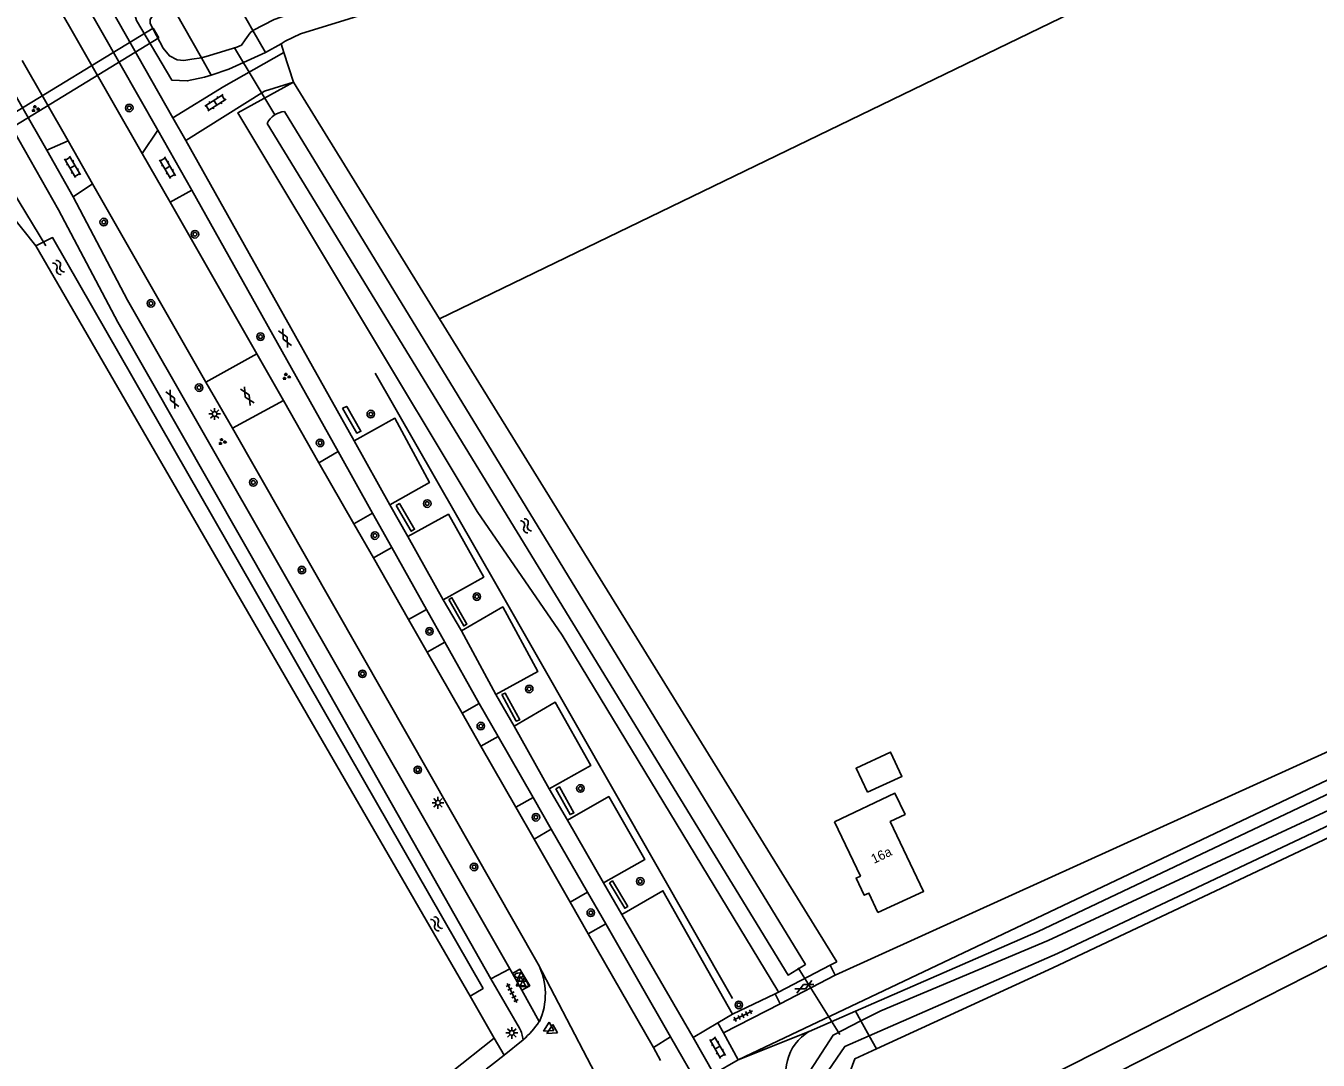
# Model space of a CAD drawing. Extents: x 134297 to 137000, y 403500 to 406000.
# Drawn here: x 136760.9 to 136897.8, y 403591.7 to 403701.3 of the extents above; entities that cross this region are included whole.
import ezdxf

# ---------------------------------------------------------------- set-up
doc = ezdxf.new("R2010")
doc.units = 0
for name, color, linetype in [('gg-afsc-erfafscheiding', 7, 'Continuous'), ('gg-anno-huisnummerreeks BGT', 7, 'Continuous'), ('gg-bbg-bijgebouw', 7, 'Continuous'), ('gg-bbg-gedigitaliseerde bebouwing', 7, 'Continuous'), ('gg-bbg-hoofdgebouw', 7, 'Continuous'), ('gg-knt-bronhoudergrens', 7, 'Continuous'), ('gg-knt-onverhard', 7, 'Continuous'), ('gg-knt-verharding', 7, 'Continuous'), ('gg-kntw-bovenkant insteek waterloop', 7, 'Continuous'), ('gg-kntw-waterlijn', 7, 'Continuous'), ('gg-kwrk-duiker nz buis', 7, 'Continuous'), ('gg-kwrk-duiker nz vlak', 7, 'Continuous'), ('gt-afsc-boombescherming', 7, 'Continuous'), ('gt-grn-groengrens', 7, 'Continuous'), ('gt-grn-vlakafsluiter', 7, 'Continuous'), ('gt-grn-weggrens', 7, 'Continuous'), ('gt-symb-boom', 7, 'Continuous'), ('gt-symb-brandkraan', 7, 'Continuous'), ('gt-symb-gesloten verharding', 7, 'Continuous'), ('gt-symb-groenvak', 7, 'Continuous'), ('gt-symb-klinker verharding', 7, 'Continuous'), ('gt-symb-lichtmast', 7, 'Continuous'), ('gt-symb-tegel verharding', 7, 'Continuous'), ('gt-symb-waterafsluiter', 7, 'Continuous'), ('gt-symb-watersymbool', 7, 'Continuous')]:
    doc.layers.add(name, color=color, linetype=linetype)

# ---------------------------------------------------------------- blocks, each defined once
blk = doc.blocks.new('gt0-BOOM')
at = {"layer": 'gt-symb-boom'}
for radius in [0.4, 0.2]:
    blk.add_circle((0, 0), radius, dxfattribs=at)
blk = doc.blocks.new('gt0-TEG1')
at = {"layer": 'gt-symb-tegel verharding'}
for p, q in [((-1.12, 0), (1.12, 0)), ((-0.9, -0.25), (-0.9, 0.25)), ((-0.45, -0.25), (-0.45, 0.25)), ((0, -0.25), (0, 0.25)), ((0.45, -0.25), (0.45, 0.25)), ((0.9, -0.25), (0.9, 0.25))]:
    blk.add_line(p, q, dxfattribs=at)
blk = doc.blocks.new('gt0-KL1')
at = {"layer": 'gt-symb-klinker verharding'}
for p, q in [((-1.15, 0.3), (1.15, 0.3)), ((-1, -0.3), (-1, 0.3)), ((-0.5, 0.3), (-0.5, 0.45)), ((0, -0.3), (0, 0.3)), ((0.5, 0.3), (0.5, 0.45)), ((1, -0.3), (1, 0.3)), ((-1.15, -0.3), (1.15, -0.3)), ((-0.5, -0.45), (-0.5, -0.3)), ((0.5, -0.45), (0.5, -0.3))]:
    blk.add_line(p, q, dxfattribs=at)
blk = doc.blocks.new('gt0-GESVH1')
at = {"layer": 'gt-symb-gesloten verharding'}
for p, q in [((-0.99, -0.26), (0.01, 0.24)), ((0.01, -0.26), (-0.99, 0.24)), ((0.01, 0.24), (1.01, -0.26)), ((1.01, 0.24), (0.01, -0.26))]:
    blk.add_line(p, q, dxfattribs=at)
blk = doc.blocks.new('gt0-BR')
at = {"layer": 'gt-symb-brandkraan'}
for centre, radius, start, end in [((-0.24, 0), 0.206, 107.5669, 252.4331), ((0.6, -2.66), 3, 106.892, 107.5669), ((0, -0.69), 0.938, 73.108, 106.892), ((-0.6, -2.66), 3, 72.4331, 73.108), ((0.24, 0), 0.206, 287.567, 72.4331), ((0.6, 2.66), 3, 252.4331, 253.108), ((0, 0.69), 0.938, 253.108, 286.8921), ((-0.6, 2.66), 3, 286.8921, 287.567)]:
    blk.add_arc(centre, radius, start, end, dxfattribs=at)
blk = doc.blocks.new('gt0-WAFSL')
at = {"layer": 'gt-symb-waterafsluiter'}
for p, q in [((-0.5, -0.33), (0, 0.67)), ((0, 0.67), (0.5, -0.33)), ((0.5, -0.33), (-0.5, -0.33))]:
    blk.add_line(p, q, dxfattribs=at)
blk = doc.blocks.new('gt0-LMAST')
at = {"layer": 'gt-symb-lichtmast'}
for p, q in [((-0.18, 0.17), (-0.45, 0.44)), ((-0.01, 0.25), (-0.01, 0.62)), ((0.17, 0.17), (0.44, 0.44)), ((-0.26, 0), (-0.63, 0)), ((-0.18, -0.18), (-0.45, -0.45)), ((-0.01, -0.25), (-0.01, -0.63)), ((0.44, -0.45), (0.17, -0.18)), ((0.24, 0), (0.62, 0))]:
    blk.add_line(p, q, dxfattribs=at)
blk.add_circle((-0.01, 0), 0.25, dxfattribs=at)
blk = doc.blocks.new('gt0-WA')
at = {"layer": 'gt-symb-watersymbool'}
for centre, start, end in [((-0.32, 0.02), 28.0725, 151.9275), ((0.43, 0.42), 208.0725, 331.9275), ((-0.32, -0.43), 28.0725, 151.9275), ((0.43, -0.03), 208.0725, 331.9275)]:
    blk.add_arc(centre, 0.425, start, end, dxfattribs=at)
blk = doc.blocks.new('gt0-GRVAK')
at = {"layer": 'gt-symb-groenvak'}
for p, q in [((-0.11, 0.19), (-0.23, 0.24)), ((-0.18, 0.15), (0.09, 0.15)), ((-0.09, 0.21), (-0.16, 0.32)), ((-0.05, 0.21), (-0.05, 0.39)), ((0, 0.21), (0.06, 0.32)), ((0.01, 0.19), (0.13, 0.24)), ((0.26, -0.05), (0.2, 0.06)), ((0.3, -0.05), (0.3, 0.13)), ((0.35, -0.05), (0.41, 0.06)), ((-0.24, -0.23), (-0.36, -0.18)), ((-0.32, -0.26), (-0.05, -0.26)), ((-0.23, -0.21), (-0.29, -0.09)), ((-0.18, -0.2), (-0.18, -0.02)), ((-0.14, -0.21), (-0.07, -0.09)), ((-0.12, -0.23), (0, -0.18)), ((0.24, -0.07), (0.12, -0.02)), ((0.17, -0.11), (0.44, -0.11)), ((0.37, -0.07), (0.49, -0.02))]:
    blk.add_line(p, q, dxfattribs=at)

msp = doc.modelspace()

# ---------------------------------------------------------------- linework, layer by layer
at = {"layer": 'gg-afsc-erfafscheiding'}
for q in [(136797.89, 403664.49), (136835.74, 403598.27)]:
    msp.add_line((136810.83, 403641.95), q, dxfattribs=at)
at = {"layer": 'gg-bbg-bijgebouw'}
msp.add_lwpolyline([(136850.05, 403620.11), (136848.82, 403622.65), (136852.49, 403624.36), (136853.69, 403621.79), (136850.05, 403620.11)], dxfattribs=at)
at = {"layer": 'gg-bbg-gedigitaliseerde bebouwing'}
msp.add_lwpolyline([(136846.56, 403616.96), (136852.94, 403620), (136854.02, 403617.76), (136852.44, 403617), (136855.98, 403609.61), (136851.13, 403607.38)], dxfattribs=at)
at = {"layer": 'gg-bbg-hoofdgebouw'}
msp.add_lwpolyline([(136851.13, 403607.38), (136850.18, 403609.43), (136849.69, 403609.2), (136848.83, 403611.01), (136849.29, 403611.23), (136846.56, 403616.96)], dxfattribs=at)
at = {"layer": 'gg-knt-bronhoudergrens'}
msp.add_line((136761.94, 403677.98), (136757.48, 403683.6), dxfattribs=at)
msp.add_lwpolyline([(136804.72, 403670.25), (136922.89, 403727.53), (136948.48, 403735.49), (136972.38, 403746.38), (137000, 403761.19)], dxfattribs=at)
at = {"layer": 'gg-knt-onverhard'}
msp.add_line((136836.35, 403591.75), (137000, 403669.55), dxfattribs=at)
for points in [[(136846.62, 403600.72), (136864.98, 403609.06), (136937.04, 403641.78), (137000, 403672.86)], [(137000, 403651.88), (136926.75, 403614.91), (136915.2, 403613.35), (136861.96, 403586.32), (136863.28, 403583.72), (136916.67, 403610.83), (136928.06, 403612.07), (137000, 403647.8)]]:
    msp.add_lwpolyline(points, dxfattribs=at)
at = {"layer": 'gg-knt-verharding'}
for p, q in [((136730.84, 403771.71), (136776.48, 403691.56)), ((136729.23, 403770.34), (136774.89, 403690.26)), ((136726.83, 403768.98), (136773.23, 403687.76)), ((136788.21, 403698.47), (136781.87, 403694.86)), ((136788.21, 403698.47), (136789.24, 403695.32)), ((136757.66, 403697.63), (136763.11, 403688.11)), ((136760.51, 403697.64), (136765.37, 403689.12)), ((136776.48, 403691.56), (136781.87, 403694.86)), ((136777.83, 403689.16), (136786.18, 403694.38)), ((136776.48, 403691.56), (136777.83, 403689.16)), ((136773.23, 403687.76), (136774.89, 403690.26)), ((136778.46, 403683.9), (136774.89, 403690.26)), ((136765.37, 403689.12), (136763.11, 403688.11)), ((136765.37, 403689.12), (136767.97, 403684.57)), ((136777.83, 403689.16), (136795.66, 403657.34)), ((136765.92, 403683.19), (136763.11, 403688.11)), ((136776.18, 403682.61), (136773.23, 403687.76)), ((136765.92, 403683.19), (136767.97, 403684.57)), ((136767.97, 403684.57), (136779.97, 403663.56)), ((136778.46, 403683.9), (136776.18, 403682.61)), ((136793.98, 403656.19), (136778.46, 403683.9)), ((136785.35, 403666.55), (136776.18, 403682.61)), ((136779.97, 403663.56), (136785.35, 403666.55)), ((136788.17, 403661.61), (136785.35, 403666.55)), ((136779.97, 403663.56), (136782.77, 403658.67)), ((136788.17, 403661.61), (136782.77, 403658.67)), ((136791.93, 403655.02), (136788.17, 403661.61)), ((136782.77, 403658.67), (136798.96, 403630.33)), ((136795.66, 403657.34), (136799.46, 403650.57)), ((136793.98, 403656.19), (136791.93, 403655.02)), ((136797.62, 403649.68), (136793.98, 403656.19)), ((136795.62, 403648.56), (136791.93, 403655.02)), ((136799.46, 403650.57), (136801.35, 403647.2)), ((136795.62, 403648.56), (136797.62, 403649.68)), ((136799.65, 403646.05), (136797.62, 403649.68)), ((136797.7, 403644.93), (136795.62, 403648.56)), ((136801.35, 403647.2), (136805.1, 403640.49)), ((136799.65, 403646.05), (136797.7, 403644.93)), ((136801.43, 403638.4), (136797.7, 403644.93)), ((136803.33, 403639.48), (136799.65, 403646.05)), ((136803.33, 403639.48), (136801.43, 403638.4)), ((136805.29, 403635.99), (136803.33, 403639.48)), ((136805.1, 403640.49), (136807.04, 403637.2)), ((136803.41, 403634.94), (136801.43, 403638.4)), ((136810.69, 403630.48), (136807.04, 403637.2)), ((136803.41, 403634.94), (136805.29, 403635.99)), ((136808.92, 403629.52), (136805.29, 403635.99)), ((136807.1, 403628.48), (136803.41, 403634.94)), ((136798.96, 403630.33), (136815.17, 403601.88)), ((136810.69, 403630.48), (136812.61, 403627.11)), ((136807.1, 403628.48), (136808.92, 403629.52)), ((136809.1, 403624.98), (136807.1, 403628.48)), ((136810.92, 403626.02), (136808.92, 403629.52)), ((136816.34, 403620.48), (136812.61, 403627.11)), ((136809.1, 403624.98), (136810.92, 403626.02)), ((136814.63, 403619.55), (136810.92, 403626.02)), ((136812.8, 403618.51), (136809.1, 403624.98)), ((136816.34, 403620.48), (136818.25, 403617.16)), ((136812.8, 403618.51), (136814.63, 403619.55)), ((136816.55, 403616.19), (136814.63, 403619.55)), ((136814.72, 403615.14), (136812.8, 403618.51)), ((136814.72, 403615.14), (136816.55, 403616.19)), ((136820.38, 403609.53), (136816.55, 403616.19)), ((136822.09, 403610.52), (136818.25, 403617.16)), ((136818.53, 403608.47), (136814.72, 403615.14)), ((136820.38, 403609.53), (136818.53, 403608.47)), ((136822.32, 403606.17), (136820.38, 403609.53)), ((136822.09, 403610.52), (136824.01, 403607.17)), ((136820.45, 403605.1), (136818.53, 403608.47)), ((136824.01, 403607.17), (136831.56, 403594.14)), ((136822.32, 403606.17), (136820.45, 403605.1)), ((136820.45, 403605.1), (136827.36, 403593.05)), ((136822.32, 403606.17), (136829.19, 403594.21)), ((136812.17, 403601.41), (136810.13, 403600.34)), ((136812.17, 403601.41), (136812.44, 403600.92)), ((136840.61, 403598.92), (136846.1, 403601.8)), ((136846.1, 403601.8), (136846.62, 403600.72)), ((136813.19, 403595.12), (136810.13, 403600.34)), ((136812.44, 403600.92), (136813.43, 403599.14)), ((136846.62, 403600.72), (136840.8, 403597.69)), ((136813.43, 403599.14), (136815.28, 403595.81)), ((136840.26, 403598.74), (136835.74, 403596.59)), ((136840.26, 403598.74), (136840.61, 403598.92)), ((136840.8, 403597.69), (136840.26, 403598.74)), ((136834.77, 403594.61), (136840.8, 403597.69)), ((136834.18, 403595.67), (136832.87, 403594.9)), ((136835.74, 403596.59), (136834.18, 403595.67)), ((136834.77, 403594.61), (136834.18, 403595.67)), ((136829.19, 403594.21), (136833.31, 403587.05)), ((136832.87, 403594.9), (136831.56, 403594.14)), ((136831.56, 403594.14), (136833.77, 403590.29)), ((136836.35, 403591.75), (136834.77, 403594.61)), ((136813.58, 403593.88), (136811.54, 403592.26)), ((136827.36, 403593.05), (136828.13, 403591.7)), ((136833.77, 403590.29), (136836.35, 403591.75))]:
    msp.add_line(p, q, dxfattribs=at)
for points in [[(136755.93, 403696.64), (136764.35, 403681.81), (136770.64, 403669.9), (136787.06, 403641.14), (136810.13, 403600.34)], [(136812.17, 403601.41), (136771.65, 403672.23), (136765.92, 403683.19)], [(136795.66, 403657.34), (136799.99, 403659.73), (136803.64, 403652.91), (136799.46, 403650.57)], [(136801.35, 403647.2), (136805.65, 403649.56), (136809.39, 403642.9), (136805.1, 403640.49)], [(136807.04, 403637.2), (136811.4, 403639.74), (136815.13, 403632.91), (136810.69, 403630.48)], [(136812.61, 403627.11), (136816.95, 403629.66), (136820.75, 403622.95), (136816.34, 403620.48)], [(136818.25, 403617.16), (136822.63, 403619.65), (136826.44, 403612.98), (136822.09, 403610.52)], [(136824.01, 403607.17), (136828.37, 403609.68), (136835.74, 403596.59)], [(136812.44, 403600.92), (136813.22, 403601.35), (136814.26, 403599.6), (136813.43, 403599.14)], [(136811.54, 403592.26), (136810.43, 403591.37), (136809.64, 403590.78)]]:
    msp.add_lwpolyline(points, dxfattribs=at)
for centre, radius, start, end in [((136808.86, 403598.73), 7.06, 335.5972, 26.5732), ((136805.5, 403602.7), 11.96, 312.4913, 324.8265), ((136808.8, 403593.06), 4.85, 9.7406, 25.1201)]:
    msp.add_arc(centre, radius, start, end, dxfattribs=at)
at = {"layer": 'gg-kntw-bovenkant insteek waterloop'}
for p, q in [((136787.94, 403699.4), (136786.28, 403698.49)), ((136789.24, 403695.32), (136804.72, 403670.25)), ((136761.94, 403677.98), (136807.94, 403598.49)), ((136804.72, 403670.25), (136846.79, 403602.14)), ((136848.76, 403596.9), (136868.12, 403605.37)), ((136846.79, 403602.14), (136846.1, 403601.8)), ((136851, 403592.94), (136869.65, 403601.51)), ((136840.53, 403599.07), (136840.61, 403598.92)), ((136843.85, 403594.75), (136848.76, 403596.9))]:
    msp.add_line(p, q, dxfattribs=at)
for points in [[(136787.94, 403699.4), (136788.35, 403699.67), (136789.97, 403700.46), (136800.3, 403703.64), (136833.32, 403713.78), (136872.7, 403726.18), (136901.79, 403735.3), (136916.15, 403739.62), (136925.98, 403742.87), (136932.43, 403745.69)], [(136780.53, 403696.09), (136779.81, 403695.85), (136778, 403695.47), (136776.36, 403695.53), (136772.6, 403701.86), (136772.43, 403702.46), (136772.46, 403702.98)], [(136786.28, 403698.49), (136782.38, 403696.7), (136780.53, 403696.09)], [(136789.24, 403695.32), (136783.35, 403692.09), (136808.71, 403649.86), (136817.71, 403636.74), (136840.53, 403599.07)], [(136807.94, 403598.49), (136809.32, 403599.33), (136763.73, 403678.86), (136761.94, 403677.98)], [(136868.12, 403605.37), (136986.72, 403661.63), (137000, 403668.21)], [(136869.65, 403601.51), (136942.38, 403635.87), (136979.91, 403653.86), (136993.59, 403660.51), (137000, 403663.51)], [(136851.86, 403580.72), (136847.45, 403588.5), (136848.68, 403591.88), (136851, 403592.94)]]:
    msp.add_lwpolyline(points, dxfattribs=at)
msp.add_arc((136846.46, 403590.41), 5.07, 121.1024, 209.5638, dxfattribs=at)
at = {"layer": 'gg-kntw-waterlijn'}
for points in [[(136784.92, 403700.8), (136787.19, 403701.98), (136791.98, 403703.64), (136814.18, 403710.58), (136852.51, 403722.56), (136895.25, 403735.63), (136919.74, 403743.36), (136925.65, 403745.28), (136927.75, 403746.01), (136929.62, 403746.71), (136931.53, 403747.52)], [(136776.72, 403702.8), (136775.1, 403702.48), (136774.26, 403702.27), (136774.06, 403701.96), (136774.06, 403701.56), (136775.44, 403698.94), (136776.1, 403698.12), (136776.94, 403697.69), (136777.62, 403697.64), (136778.47, 403697.78), (136779.49, 403697.91)], [(136779.49, 403697.91), (136780.35, 403698.16), (136783.25, 403699.05), (136783.72, 403699.26), (136784.11, 403699.82), (136784.67, 403700.54), (136784.92, 403700.8)], [(136786.46, 403690.96), (136841.62, 403600.74), (136843.47, 403601.87), (136788.29, 403692.22)], [(136849.34, 403595.88), (136851.44, 403596.96), (136869.16, 403604.39), (136908.8, 403622.81), (136965.84, 403650.17), (137000, 403666.81)], [(136850.22, 403594.31), (136870.15, 403603.01), (136909.4, 403621.55), (136966.45, 403648.91), (137000, 403665.25)], [(136848.64, 403578.97), (136847.95, 403580.17), (136845.03, 403585.68), (136843.54, 403589.96), (136846.41, 403594.39), (136849.34, 403595.88)], [(136850.22, 403594.31), (136847.63, 403593.18), (136845.5, 403590.03), (136847.48, 403585.31), (136850.52, 403580)]]:
    msp.add_lwpolyline(points, dxfattribs=at)
msp.add_arc((136788.5, 403689.96), 2.27, 95.2759, 153.7092, dxfattribs=at)
at = {"layer": 'gg-kwrk-duiker nz buis'}
for p, q in [((136782.99, 403698.97), (136787.28, 403691.87)), ((136763.03, 403678), (136758.76, 403684.99)), ((136842.71, 403601.52), (136847.12, 403594.45))]:
    msp.add_line(p, q, dxfattribs=at)
at = {"layer": 'gg-kwrk-duiker nz vlak'}
for p, q in [((136755.94, 403689.82), (136774.37, 403701.05)), ((136774.37, 403701.05), (136774.98, 403700.01)), ((136756.57, 403688.8), (136774.98, 403700.01))]:
    msp.add_line(p, q, dxfattribs=at)
at = {"layer": 'gt-afsc-boombescherming'}
for points in [[(136794.45, 403660.78), (136794.89, 403660.98), (136796.39, 403658.35), (136795.95, 403658.15), (136794.45, 403660.78)], [(136800.11, 403650.48), (136800.46, 403650.68), (136802.06, 403647.96), (136801.72, 403647.76), (136800.11, 403650.48)], [(136805.71, 403640.53), (136806.03, 403640.72), (136807.6, 403637.91), (136807.28, 403637.72), (136805.71, 403640.53)], [(136811.31, 403630.47), (136811.68, 403630.61), (136813.21, 403627.79), (136812.84, 403627.65), (136811.31, 403630.47)], [(136817.03, 403620.48), (136817.42, 403620.67), (136818.94, 403617.94), (136818.54, 403617.75), (136817.03, 403620.48)], [(136822.72, 403610.51), (136823.03, 403610.72), (136824.64, 403608.02), (136824.33, 403607.81), (136822.72, 403610.51)]]:
    msp.add_lwpolyline(points, dxfattribs=at)
at = {"layer": 'gt-grn-groengrens'}
for p, q in [((136789.24, 403695.32), (136786.18, 403694.38)), ((136810.5, 403594.07), (136807.94, 403598.49)), ((136836.35, 403591.75), (136843.85, 403594.75)), ((136805.88, 403590.4), (136810.5, 403594.07)), ((136810.5, 403594.07), (136811.54, 403592.26))]:
    msp.add_line(p, q, dxfattribs=at)
at = {"layer": 'gt-grn-vlakafsluiter'}
for p, q in [((136783.13, 403703.99), (136784.92, 403700.8)), ((136776.72, 403702.8), (136779.49, 403697.91)), ((136784.92, 403700.8), (136786.28, 403698.49)), ((136788.21, 403698.47), (136787.94, 403699.4)), ((136779.49, 403697.91), (136780.53, 403696.09)), ((136848.76, 403596.9), (136849.34, 403595.88)), ((136849.34, 403595.88), (136850.22, 403594.31)), ((136850.22, 403594.31), (136851, 403592.94))]:
    msp.add_line(p, q, dxfattribs=at)
at = {"layer": 'gt-grn-weggrens'}
for p, q in [((136822.12, 403588.57), (136815.17, 403601.88)), ((136827.36, 403593.05), (136829.19, 403594.21))]:
    msp.add_line(p, q, dxfattribs=at)

# ---------------------------------------------------------------- block references
at = {"layer": 'gt-symb-boom'}
for p in [(136771.85, 403692.6), (136769.15, 403680.51), (136778.81, 403679.22), (136774.15, 403671.9), (136785.75, 403668.37), (136779.24, 403662.97), (136797.43, 403660.17), (136792.06, 403657.12), (136784.99, 403652.93), (136803.41, 403650.69), (136797.87, 403647.3), (136790.13, 403643.65), (136808.66, 403640.83), (136803.65, 403637.16), (136796.55, 403632.65), (136814.21, 403631.05), (136809.08, 403627.12), (136802.41, 403622.48), (136819.63, 403620.51), (136814.92, 403617.46), (136808.37, 403612.2), (136825.97, 403610.67), (136820.73, 403607.34), (136836.41, 403597.58)]:
    msp.add_blockref('gt0-BOOM', p, dxfattribs=at)
at = {"layer": 'gt-symb-brandkraan'}
msp.add_blockref('gt0-BR', (136813.14, 403600.72), dxfattribs=at)
at = {"layer": 'gt-symb-gesloten verharding'}
for p, rotation in [((136788.35, 403668.2), 117.97472992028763), ((136776.42, 403661.73), 117.9747299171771), ((136784.35, 403662.09), -59.3310733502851), ((136843.34, 403599.51), 26.436872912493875)]:
    msp.add_blockref('gt0-GESVH1', p, dxfattribs=dict(at, rotation=rotation))
at = {"layer": 'gt-symb-groenvak'}
for p in [(136761.9, 403692.51), (136788.48, 403664.14), (136781.68, 403657.24)]:
    msp.add_blockref('gt0-GRVAK', p, dxfattribs=at)
at = {"layer": 'gt-symb-klinker verharding'}
for p, rotation in [((136780.98, 403693.16), -147.9946167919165), ((136765.84, 403686.36), 120.00072778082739), ((136775.9, 403686.27), 120.00072778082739), ((136834.16, 403593.06), 120.000727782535)]:
    msp.add_blockref('gt0-KL1', p, dxfattribs=dict(at, rotation=rotation))
at = {"layer": 'gt-symb-lichtmast'}
for p in [(136780.9, 403660.18), (136804.55, 403618.99), (136812.37, 403594.61)]:
    msp.add_blockref('gt0-LMAST', p, dxfattribs=at)
at = {"layer": 'gt-symb-tegel verharding'}
for p, rotation in [((136812.39, 403598.84), -62.87123394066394), ((136836.84, 403596.45), 26.436872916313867)]:
    msp.add_blockref('gt0-TEG1', p, dxfattribs=dict(at, rotation=rotation))
at = {"layer": 'gt-symb-waterafsluiter'}
for p in [(136813.37, 403600.42), (136813.31, 403599.93), (136813.72, 403599.85)]:
    msp.add_blockref('gt0-WAFSL', p, dxfattribs=at)
at = {"layer": 'gt-symb-waterafsluiter', "rotation": 120.33480582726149}
for p in [(136816.29, 403595.14), (136816.67, 403594.9)]:
    msp.add_blockref('gt0-WAFSL', p, dxfattribs=at)
at = {"layer": 'gt-symb-watersymbool'}
for p, rotation in [((136764.39, 403675.65), 126.9958977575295), ((136813.84, 403648.38), -58.45632657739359), ((136804.42, 403606.11), 126.9958977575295)]:
    msp.add_blockref('gt0-WA', p, dxfattribs=dict(at, rotation=rotation))

# ---------------------------------------------------------------- texts
at = {"layer": 'gg-anno-huisnummerreeks BGT'}
msp.add_text('16a', height=1, rotation=25.5, dxfattribs=at).set_placement((136850.71, 403612.51))

doc.saveas('drawing.dxf')
